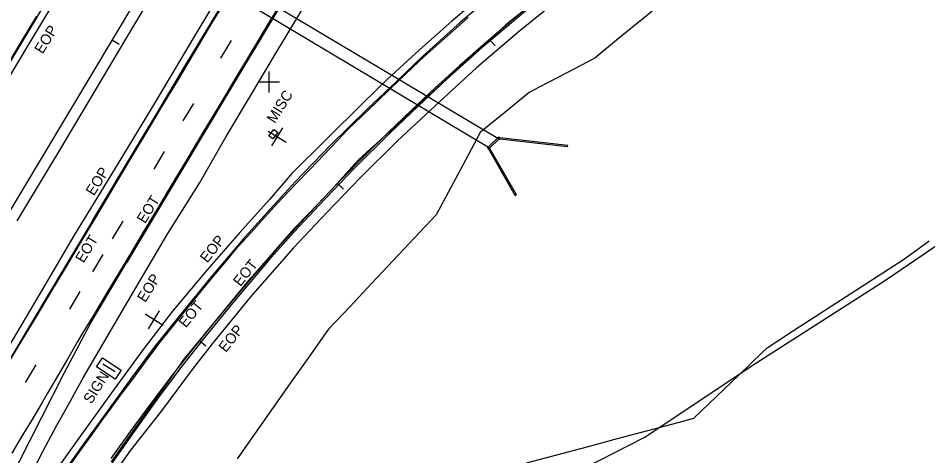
# Model space of a CAD drawing. Extents: x 2132221 to 2141942, y 535736 to 547298.
# Drawn here: x 2137298 to 2137732.2, y 539223.5 to 539432.5 of the extents above; entities that cross this region are included whole.
import ezdxf

# ---------------------------------------------------------------- set-up
doc = ezdxf.new("R2010")
doc.units = 0
for name, color, linetype in [('RD_EX_BldgApp', 7, 'Continuous'), ('RD_EX_BldgApp_txCode', 7, 'Continuous'), ('RD_EX_Conc', 7, 'Continuous'), ('RD_EX_GuardRail', 7, 'Continuous'), ('RD_EX_H2O', 7, 'Continuous'), ('RD_EX_Misc', 7, 'Continuous'), ('RD_EX_Misc_txCode', 7, 'Continuous'), ('RD_EX_Road', 7, 'Continuous'), ('RD_EX_Road_txCode', 7, 'Continuous'), ('RD_EX_VEG', 7, 'Continuous'), ('RD_HC_Cl', 7, 'Continuous'), ('RD_HC_Data_Tic', 7, 'Continuous')]:
    doc.layers.add(name, color=color, linetype=linetype)

msp = doc.modelspace()

# ---------------------------------------------------------------- linework, layer by layer
at = {"layer": 'RD_EX_BldgApp'}
msp.add_line((2137338.39, 539267.41), (2137344.37, 539263.73), dxfattribs=at)
at = {"layer": 'RD_EX_Conc'}
for p, q in [((2137527.69, 539374.58), (2137173.5, 539585.79)), ((2137170.3, 539581.57), (2137523.27, 539370.49)), ((2137560.31, 539371.73), (2137527.89, 539375.32)), ((2137522.6, 539369.89), (2137523.18, 539370.23)), ((2137535.27, 539347.88), (2137522.6, 539369.89)), ((2137560.23, 539371.06), (2137560.31, 539371.73)), ((2137535.27, 539347.88), (2137535.85, 539348.21))]:
    msp.add_line(p, q, dxfattribs=at)
for points in [[(2137263.04, 539359.5), (2137275.58, 539380.34), (2137294.64, 539412.29), (2137320.12, 539454.95), (2137338.88, 539486.39), (2137364.26, 539528.76), (2137383.24, 539560.45), (2137408.68, 539602.98), (2137427.67, 539634.75), (2137453.05, 539677.2), (2137471.87, 539708.82), (2137497.19, 539751.42), (2137516.41, 539783.43), (2137541.62, 539825.46), (2137561.12, 539858.06), (2137585.95, 539899.61), (2137605.04, 539931.67), (2137630.62, 539974.42), (2137649.49, 540005.97)], [(2137333.67, 539335.96), (2137355.29, 539372.23), (2137365.06, 539388.65), (2137377.92, 539410.12), (2137399.62, 539446.12), (2137422.3, 539484.15), (2137444, 539520.34), (2137466.68, 539558.23), (2137488.53, 539594.68), (2137510.97, 539632.25), (2137532.88, 539668.78), (2137555.26, 539706.26), (2137576.91, 539742.44), (2137599.85, 539780.45), (2137621.54, 539816.61), (2137644.15, 539854.85), (2137665.88, 539890.9), (2137688.75, 539929.11), (2137713.64, 539970.82)], [(2137730.9, 539952.54), (2137709.36, 539916.37), (2137691.52, 539886.57), (2137674.64, 539858.53), (2137661.7, 539836.86), (2137649.76, 539817.01), (2137632.95, 539788.69), (2137616.77, 539761.89), (2137588.72, 539714.71), (2137563.22, 539672.35), (2137544.53, 539641.12), (2137524.37, 539607.53), (2137505.33, 539575.66), (2137487.21, 539545.55), (2137464.95, 539508.2), (2137442.94, 539471.57), (2137420.66, 539434.19), (2137398.45, 539397.12), (2137376.07, 539359.84), (2137349.68, 539315.66)], [(2137750.62, 539573.33), (2137728.53, 539562.07), (2137707.69, 539550.71), (2137692.5, 539542.14), (2137677.03, 539533.19), (2137655.6, 539519.79), (2137635.4, 539506.63), (2137620.8, 539496.82), (2137605.04, 539485.98), (2137585.32, 539471.48), (2137567.1, 539457.65), (2137553.56, 539446.85), (2137538.45, 539434.49), (2137519.49, 539418.57), (2137502.42, 539403.19), (2137489.14, 539390.68), (2137475.58, 539377.67), (2137458.33, 539360.72), (2137441.76, 539343.31), (2137429.79, 539330.42), (2137417.48, 539316.71), (2137401.29, 539297.54), (2137386.22, 539279.28)], [(2137528.33, 539446.78), (2137509.12, 539430.53), (2137491.29, 539414.5), (2137478.54, 539402.27), (2137464.75, 539389.15), (2137447.06, 539371.8), (2137430.39, 539354.51), (2137418.11, 539341.07), (2137405.41, 539327), (2137389.26, 539308.09), (2137374.18, 539289.35), (2137362.94, 539275.45)], [(2137527.94, 539375.24), (2137527.37, 539375.85), (2137521.99, 539370.54), (2137522.54, 539370), (2137527.94, 539375.24)], [(2137560.23, 539371.06), (2137527.82, 539374.66)], [(2137535.85, 539348.21), (2137523.18, 539370.23)], [(2137333.67, 539335.96), (2137310.86, 539297.96), (2137285.52, 539255.72), (2137262.8, 539217.71), (2137241.15, 539181.64), (2137218.32, 539143.58), (2137200.03, 539113.05), (2137181.55, 539082.16), (2137156.17, 539039.86), (2137139.5, 539011.87)], [(2137297.62, 539219.08), (2137309.33, 539241.89), (2137320.01, 539262.99), (2137332.61, 539287.08), (2137349.68, 539315.66)], [(2137386.22, 539279.28), (2137375.65, 539265.67), (2137364.42, 539250.49), (2137352.58, 539233.98), (2137342.73, 539219.91), (2137331.08, 539203.52), (2137316.82, 539183.44), (2137303.12, 539163.77), (2137293.03, 539149.45), (2137281.61, 539133.04), (2137267.61, 539113.07), (2137257.39, 539098.52), (2137236.65, 539069.06), (2137212.4, 539034.24), (2137197.5, 539013.03), (2137179.75, 538987.14)], [(2137362.94, 539275.45), (2137351.65, 539260.12), (2137339.72, 539243.51), (2137329.01, 539228.88), (2137318.09, 539213.54), (2137305.67, 539196.39), (2137289.35, 539173.96)]]:
    msp.add_lwpolyline(points, dxfattribs=at)
msp.add_lwpolyline([(2137344.25, 539260.12), (2137335.4, 539265.94), (2137338.26, 539270.28), (2137347.1, 539264.46)], close=True, dxfattribs=at)
at = {"layer": 'RD_EX_GuardRail'}
msp.add_lwpolyline([(2137592.36, 539832.15), (2137568.26, 539787.9), (2137548.04, 539754.27), (2137531.87, 539727.26), (2137515.31, 539699.54), (2137498.28, 539671.31), (2137474.37, 539631.17), (2137458.05, 539604.34), (2137441.86, 539577.27), (2137417.6, 539536.44), (2137400.33, 539507.43), (2137377.39, 539469.62), (2137353.17, 539429.19), (2137317.32, 539368.74), (2137297.36, 539335.79)], dxfattribs=at)
at = {"layer": 'RD_EX_H2O'}
msp.add_lwpolyline([(2137561.97, 539214.45), (2137596.87, 539232.3), (2137650.06, 539267.67), (2137712, 539307.46), (2137759.81, 539340), (2137825.98, 539388.98), (2137850.56, 539403.08), (2137868.04, 539410.05), (2137881.59, 539406.18), (2137906.4, 539387.65), (2137918.36, 539373.88), (2137920.35, 539362.47), (2137915.45, 539344.62), (2137886.46, 539286.47), (2137849.68, 539210.84)], dxfattribs=at)
at = {"layer": 'RD_EX_Misc'}
for p, q in [((2137394.76, 539413.46), (2137399.76, 539421.84)), ((2137417.81, 539397.03), (2137417.81, 539407.03)), ((2137412.81, 539402.03), (2137422.81, 539402.03)), ((2137376.78, 539383.41), (2137381.77, 539391.79)), ((2137425.89, 539373.18), (2137417.4, 539378.46)), ((2137419.01, 539371.57), (2137424.29, 539380.07)), ((2137362.92, 539360.44), (2137367.92, 539368.83)), ((2137343.06, 539327.12), (2137348.06, 539335.5)), ((2137333.58, 539311.34), (2137338.58, 539319.72)), ((2137322.66, 539293.6), (2137327.65, 539301.98)), ((2137367.13, 539285.8), (2137358.64, 539291.08)), ((2137360.25, 539284.2), (2137365.53, 539292.69)), ((2137301.55, 539258.56), (2137306.54, 539266.94))]:
    msp.add_line(p, q, dxfattribs=at)
for points in [[(2137398.81, 539444.18), (2137391.09, 539431.32), (2137389.23, 539428.22), (2137381.53, 539415.35), (2137373.83, 539402.48), (2137366.12, 539389.61), (2137358.42, 539376.74), (2137350.71, 539363.87), (2137343.01, 539351), (2137335.31, 539338.13), (2137327.6, 539325.26), (2137319.9, 539312.39), (2137313.6, 539301.86), (2137305.9, 539288.99), (2137298.19, 539276.12), (2137290.49, 539263.25)], [(2137421.71, 539437.16), (2137416.89, 539429.11), (2137412.07, 539421.06), (2137407.24, 539413.01), (2137402.42, 539404.96), (2137397.59, 539396.9), (2137392.77, 539388.85), (2137387.95, 539380.8), (2137383.12, 539372.75), (2137378.3, 539364.7), (2137373.47, 539356.65), (2137368.65, 539348.59), (2137367.82, 539347.21), (2137363, 539339.16), (2137358.18, 539331.11), (2137353.35, 539323.06), (2137348.53, 539315.01), (2137343.7, 539306.96), (2137338.88, 539298.9), (2137334.06, 539290.85), (2137329.23, 539282.8), (2137326.21, 539277.76), (2137321.48, 539269.65), (2137316.75, 539261.54), (2137312.03, 539253.43), (2137309.43, 539248.98), (2137304.61, 539240.92), (2137299.8, 539232.86), (2137294.99, 539224.8)], [(2137306.68, 539433.48), (2137299.02, 539420.58), (2137291.35, 539407.69)], [(2137321.82, 539217.77), (2137327.31, 539225.4), (2137332.8, 539233.04), (2137338.29, 539240.67), (2137341.44, 539245.06), (2137347.04, 539252.61), (2137352.65, 539260.16), (2137358.25, 539267.72), (2137363.85, 539275.27), (2137364.99, 539276.81), (2137370.87, 539284.16), (2137376.75, 539291.51), (2137382.63, 539298.85), (2137385.32, 539302.21), (2137391.34, 539309.44), (2137397.36, 539316.67), (2137402.84, 539323.25), (2137409.16, 539330.22), (2137415.49, 539337.2), (2137421.81, 539344.17), (2137424.26, 539346.87), (2137430.78, 539353.66), (2137437.3, 539360.45), (2137443.82, 539367.24), (2137450.35, 539374.03), (2137455.39, 539379.29), (2137462.19, 539385.81), (2137468.99, 539392.33), (2137475.79, 539398.85), (2137482.59, 539405.37), (2137489.39, 539411.9), (2137491.68, 539414.1), (2137498.74, 539420.35), (2137505.79, 539426.6), (2137512.85, 539432.85)], [(2137540, 539436.69), (2137530.77, 539429.31), (2137519.71, 539419.17), (2137508.66, 539409.03), (2137497.6, 539398.89), (2137486.55, 539388.76), (2137475.49, 539378.62), (2137464.43, 539368.48), (2137460.12, 539364.53), (2137450.11, 539353.35), (2137447.46, 539350.39), (2137437.03, 539339.61), (2137429.56, 539331.89), (2137419.68, 539320.61), (2137409.8, 539309.32), (2137408.75, 539308.11), (2137399.22, 539296.53), (2137389.69, 539284.94), (2137380.17, 539273.35), (2137377.08, 539269.6), (2137368.41, 539257.36), (2137359.73, 539245.13), (2137351.05, 539232.89), (2137342.37, 539220.66)]]:
    msp.add_lwpolyline(points, dxfattribs=at)
msp.add_lwpolyline([(2137421.91, 539377.94), (2137419.54, 539374.83), (2137417.7, 539376.24), (2137420.06, 539379.34)], close=True, dxfattribs=at)
at = {"layer": 'RD_EX_Road'}
for points in [[(2137262.82, 539351.95), (2137281.66, 539384.2), (2137304.23, 539421.92), (2137324.62, 539455.81), (2137346.95, 539494.12), (2137365.98, 539524.98), (2137382.97, 539552.95), (2137402.34, 539585.47), (2137421, 539616.32), (2137440.79, 539650.02), (2137458.12, 539679.26), (2137474.32, 539706.92), (2137495.73, 539742.57), (2137510.44, 539767.21), (2137528.18, 539796.71), (2137547.34, 539828.56), (2137566.47, 539860.5), (2137583.1, 539889.05), (2137601.67, 539919.51), (2137620.06, 539950.89), (2137640.86, 539984.68), (2137653.2, 540005.1)], [(2137324.83, 539328.87), (2137342.23, 539357.26), (2137362.06, 539390.06), (2137382.99, 539425.01), (2137399.53, 539452.71), (2137417.7, 539482.98), (2137434.42, 539511.01), (2137453.36, 539542.64), (2137470.34, 539571.3), (2137490.4, 539604.67), (2137505.05, 539629.27), (2137523.94, 539660.93), (2137544.6, 539695.33), (2137566.61, 539732.02), (2137588.55, 539768.02), (2137611.63, 539807.13), (2137631.63, 539840.98), (2137648.48, 539868.92), (2137668.45, 539902.66), (2137688.62, 539936.21), (2137708.24, 539968.78)], [(2137356.91, 539308.32), (2137369.5, 539329.65), (2137384.59, 539353.73), (2137397.29, 539376.03), (2137408.9, 539395.48), (2137420.85, 539415.41), (2137430.98, 539432.35), (2137445.95, 539457.39), (2137460.1, 539480.86), (2137475.28, 539506), (2137488.98, 539529.07), (2137502.16, 539551.03), (2137517.42, 539576.6), (2137531.09, 539599.17), (2137543.64, 539620.2), (2137556.68, 539641.88), (2137570.47, 539664.65), (2137589.03, 539695.92), (2137602.93, 539718.99), (2137615.45, 539739.96)], [(2137745.3, 539591.9), (2137723.8, 539581.28), (2137704.12, 539570.87), (2137684.77, 539559.86), (2137671.4, 539552.35), (2137653.49, 539541.21), (2137630.71, 539526.66), (2137610.19, 539513.1), (2137597.26, 539504.44), (2137574.94, 539488.13), (2137555.4, 539473.33), (2137540.71, 539461.53), (2137522.48, 539445.87), (2137504.99, 539431.11), (2137489.61, 539417.35), (2137474.28, 539403.35), (2137462.64, 539392.07), (2137445.1, 539374.65), (2137428.62, 539358.35), (2137417.89, 539345.97), (2137403.86, 539330.21), (2137388.16, 539312.34), (2137371.7, 539292.54)], [(2137742.38, 539563.73), (2137729.35, 539556.45), (2137713.2, 539547.68), (2137697.67, 539538.57), (2137681.95, 539529.85), (2137667.82, 539521.51), (2137649.27, 539509.52), (2137636.42, 539501.18), (2137619.68, 539489.93), (2137604.72, 539479.15), (2137585.17, 539464.87), (2137568.39, 539451.94), (2137554.7, 539440.32), (2137537.52, 539426.48), (2137516.7, 539408.79), (2137499.32, 539392.72), (2137478.91, 539373.82), (2137461.2, 539356.32), (2137445.38, 539339.73), (2137429.48, 539322.89), (2137408.9, 539299.43), (2137390.6, 539276.98)], [(2137136.47, 539012.76), (2137143.68, 539025.32), (2137166.46, 539063.47), (2137188.17, 539100.06), (2137206.31, 539130.4), (2137225.59, 539162.23), (2137242.51, 539190.02), (2137260.51, 539220.13), (2137282.76, 539257.55), (2137308.14, 539300.44), (2137324.83, 539328.87)], [(2137371.7, 539292.54), (2137357.19, 539273.64), (2137342.52, 539253.53), (2137326.08, 539230.83), (2137315.06, 539215.22), (2137302.83, 539198.78), (2137300.08, 539200.59), (2137299.94, 539202.26), (2137299.34, 539204.04), (2137300.12, 539207.5), (2137301.1, 539209.13), (2137302.41, 539210.39), (2137308.71, 539223.55), (2137316.49, 539238.12), (2137321.07, 539246.25), (2137329.02, 539260.71), (2137341.13, 539281.49), (2137350.29, 539297.24), (2137356.91, 539308.32)], [(2137390.6, 539276.98), (2137381.06, 539264.66), (2137366.46, 539244.94), (2137351.69, 539226.13), (2137339.88, 539209.47), (2137328.84, 539193.7), (2137317.64, 539177.92), (2137305.73, 539161.76), (2137291.11, 539139.83), (2137277.39, 539118.75), (2137261.14, 539093.92), (2137244.5, 539069.57), (2137229.53, 539048.64), (2137216.9, 539030.62), (2137196.32, 539001.16), (2137178.95, 538975.86), (2137168.15, 538960.62)]]:
    msp.add_lwpolyline(points, dxfattribs=at)
at = {"layer": 'RD_EX_VEG'}
for points in [[(2137607.68, 539441.82), (2137596.1, 539432.27), (2137584.53, 539422.73), (2137573.21, 539413.39), (2137559.91, 539406.44), (2137546.62, 539399.49), (2137541.89, 539397.02), (2137530.29, 539387.51), (2137518.7, 539377.99), (2137518.52, 539377.85), (2137511.44, 539364.62), (2137504.36, 539351.4), (2137497.49, 539338.56), (2137487.21, 539327.64), (2137476.94, 539316.71), (2137466.66, 539305.78), (2137456.39, 539294.85), (2137446.11, 539283.92), (2137445.6, 539283.38), (2137436.98, 539271.11), (2137428.35, 539258.84), (2137419.73, 539246.57), (2137411.1, 539234.3), (2137402.48, 539222.02)], [(2137540.63, 539220.07), (2137555.13, 539223.95), (2137569.62, 539227.83), (2137584.11, 539231.7), (2137598.6, 539235.58), (2137613.09, 539239.46), (2137620.49, 539241.44), (2137631.3, 539251.84), (2137642.11, 539262.24), (2137652.92, 539272.64), (2137655.48, 539275.11), (2137668.07, 539283.27), (2137680.66, 539291.42), (2137693.25, 539299.58), (2137705.84, 539307.73), (2137718.43, 539315.89), (2137720.65, 539317.33), (2137732.81, 539326.12)]]:
    msp.add_lwpolyline(points, dxfattribs=at)
at = {"layer": 'RD_HC_Cl'}
msp.add_line((2139719.79, 543396.28), (2136851.48, 538600.7), dxfattribs=at)
msp.add_arc((2138238.15, 538594.85), 1093.7, 40.39109, 144.99812, dxfattribs=at)
at = {"layer": 'RD_HC_Data_Tic'}
for p, q in [((2137342.8, 539422.15), (2137346.23, 539420.09)), ((2137523.03, 539422.36), (2137525.65, 539419.34)), ((2137450.46, 539353.61), (2137453.34, 539350.84)), ((2137384.47, 539278.52), (2137387.6, 539276.02))]:
    msp.add_line(p, q, dxfattribs=at)

# ---------------------------------------------------------------- texts
at = {"layer": 'RD_EX_BldgApp_txCode'}
msp.add_text('SIGN', height=5, rotation=58.1344, dxfattribs=at).set_placement((2137332.97, 539247.94))
at = {"layer": 'RD_EX_Misc_txCode'}
for s, rotation, p in [('MISC', 58.1344, (2137420.55, 539381.93)), ('EOT', 58.1344, (2137358.52, 539334.09)), ('EOT', 58.1344, (2137329.19, 539315.26)), ('EOT', 51.1577, (2137404.03, 539304.03)), ('EOT', 51.1577, (2137378.04, 539284.33))]:
    msp.add_text(s, height=5, rotation=rotation, dxfattribs=at).set_placement(p)
at = {"layer": 'RD_EX_Road_txCode'}
for rotation, p in [(58.1344, (2137309.64, 539415.1)), (58.1344, (2137334.15, 539347.34)), (51.6568, (2137388.26, 539315.29)), (58.1344, (2137358.7, 539296.43)), (51.6568, (2137397.12, 539272.53))]:
    msp.add_text('EOP', height=5, rotation=rotation, dxfattribs=at).set_placement(p)

doc.saveas('drawing.dxf')
